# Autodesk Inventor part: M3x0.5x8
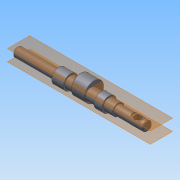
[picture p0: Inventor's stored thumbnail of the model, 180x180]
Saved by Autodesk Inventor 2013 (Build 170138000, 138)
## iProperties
Company: 한국ATC센터
Created: 2009-02
Part Number: M3x0.5x8
Document SubType Name: Modeling
Designer: KYOUNG IL JANG
Density: 7.86 g/cm^3
Mass: 246.092 g
Surface Area: 95.1288 cm^2
Volume: 31.3094 cm^3
Material: 강, 연강
Vendor: CBT Solutions
Author: KYOUNG IL JANG
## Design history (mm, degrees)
sketch "스케치1"
  geometry: L1 (-84.5, 0)-(84.5, 0); L2 (-84.5, 0)-(-84.5, 6); L3 (-84.5, 6)-(-30.5, 6); L4 (-30.5, 6)-(-30.5, 9.5); L5 (-30.5, 9.5)-(-15.5, 9.5); L6 (-15.5, 9.5)-(-15.5, 7.5); L7 (-15.5, 7.5)-(46.5, 7.5); L8 (84.5, 6)-(84.5, 0); L9 (34.5, 7.5)-(34.5, 9.5); L10 (34.5, 9.5)-(24.5, 9.5); L11 (24.5, 9.5)-(24.5, 7.5); L12 (46.5, 7.5)-(46.5, 6); L13 (46.5, 6)-(84.5, 6); 2 further points
  constraints: 26 end point, 6 parallel, 6 perpendicular, 2 point on line, 1 coincident, 1 horizontal, 1 midpoint
  dimensions: "d1" = 12 diameter of L3 L1; "d2" = 15 diameter of L7 L1; "d4" = 15 distance of L4.end L5.end; "d5" = 19 diameter of L5 L1; "d24" = 10 distance of L9.end L10.end; "d25" = 19 diameter of L10 L1; "d27" = 40 distance between parallel lines of L11 L6; "d28" = 54 distance of L2.end L3.end; "d29" = 50 distance between parallel lines of L8 L9; "d41" = 38 distance between parallel lines of L8 L12; "d42" = 12 diameter of L13 L1
revolve "회전1" stored, may be unused: angle "d6" = 90 deg
node "작업 평면1"
sketch "스케치2"
  geometry: C1 r 7.5 at (0, 0) reference; C2 r 12.5 at (0, 4.5); 1 further point
  constraints: 1 centre point, 1 vertical alignment
  dimensions: "d8" = 4.5 distance of point (0, 0) C2.centre; "d9" = 25 diameter of C2
extrude "돌출1" join sketch "스케치2" distance "d10" = 18; taper "d11" = 0 deg
chamfer "모따기1" distance "d12" = 1; stored, may be unused: second distance "d13" = 2, angle "d14" = 45 deg
chamfer "모따기2" distance "d15" = 0.5; stored, may be unused: second distance "d16" = 2, angle "d17" = 45 deg
node "작업 평면2"
sketch "스케치3"
  geometry: L1 (4, -2)-(18, -2); L2 (18, 2)-(4, 2); L3 (27, 5)-(27, -5) reference; A1 r 2 centre (18, 0) between (18, -2) and (18, 2); A2 r 2 centre (4, 0) between (4, 2) and (4, -2); 2 further points
  constraints: 4 end point, 4 point on circle, 4 tangent, 2 centre point, 1 horizontal, 1 horizontal alignment, 1 midpoint, 1 parallel
  dimensions: "d18" = 7 distance edge to line of A1 L3; "d19" = 4 distance between parallel lines of L2 L1; "d20" = 18 dimension on A1 A2
extrude "돌출2" cut sketch "스케치3" distance "d21" = 2.5; taper "d22" = 0 deg
revolve "회전2" stored, may be unused: angle "d26" = 90 deg
node "작업 평면3"
sketch "스케치4"
  geometry: L1 (44, 5)-(44, -5) reference; 2 further points
  constraints: 1 horizontal alignment
  dimensions: "d30" = 12 distance from line of point (32, 0) L1
hole "구멍1" sketch "스케치4" at (32, 0) diameter "d31" = 9; stored, may be unused: countersink angle "d35" = 90 deg, drill point angle "d37" = 118 deg; dims "d32" = 6, "d33" = 14, "d34" = 3, "d36" = 8
node "작업 평면4"
sketch "스케치5"
  geometry: C1 r 8 at (32, 0); A1 r 4.5 centre (32, 0) between (29.879, 3.969) and (29.879, -3.969) reference; A2 r 4.5 centre (32, 0) between (34.121, -3.969) and (34.121, 3.969) reference; 1 further point
  constraints: 2 horizontal alignment, 1 centre point, 1 coincident
  dimensions: "d38" = 16 diameter of C1
extrude "돌출3" cut sketch "스케치5" distance "d39" = 3; taper "d40" = 0 deg
node "솔리드1"
node "투영된 루프1"
other parameters: "d7" = 8.5
